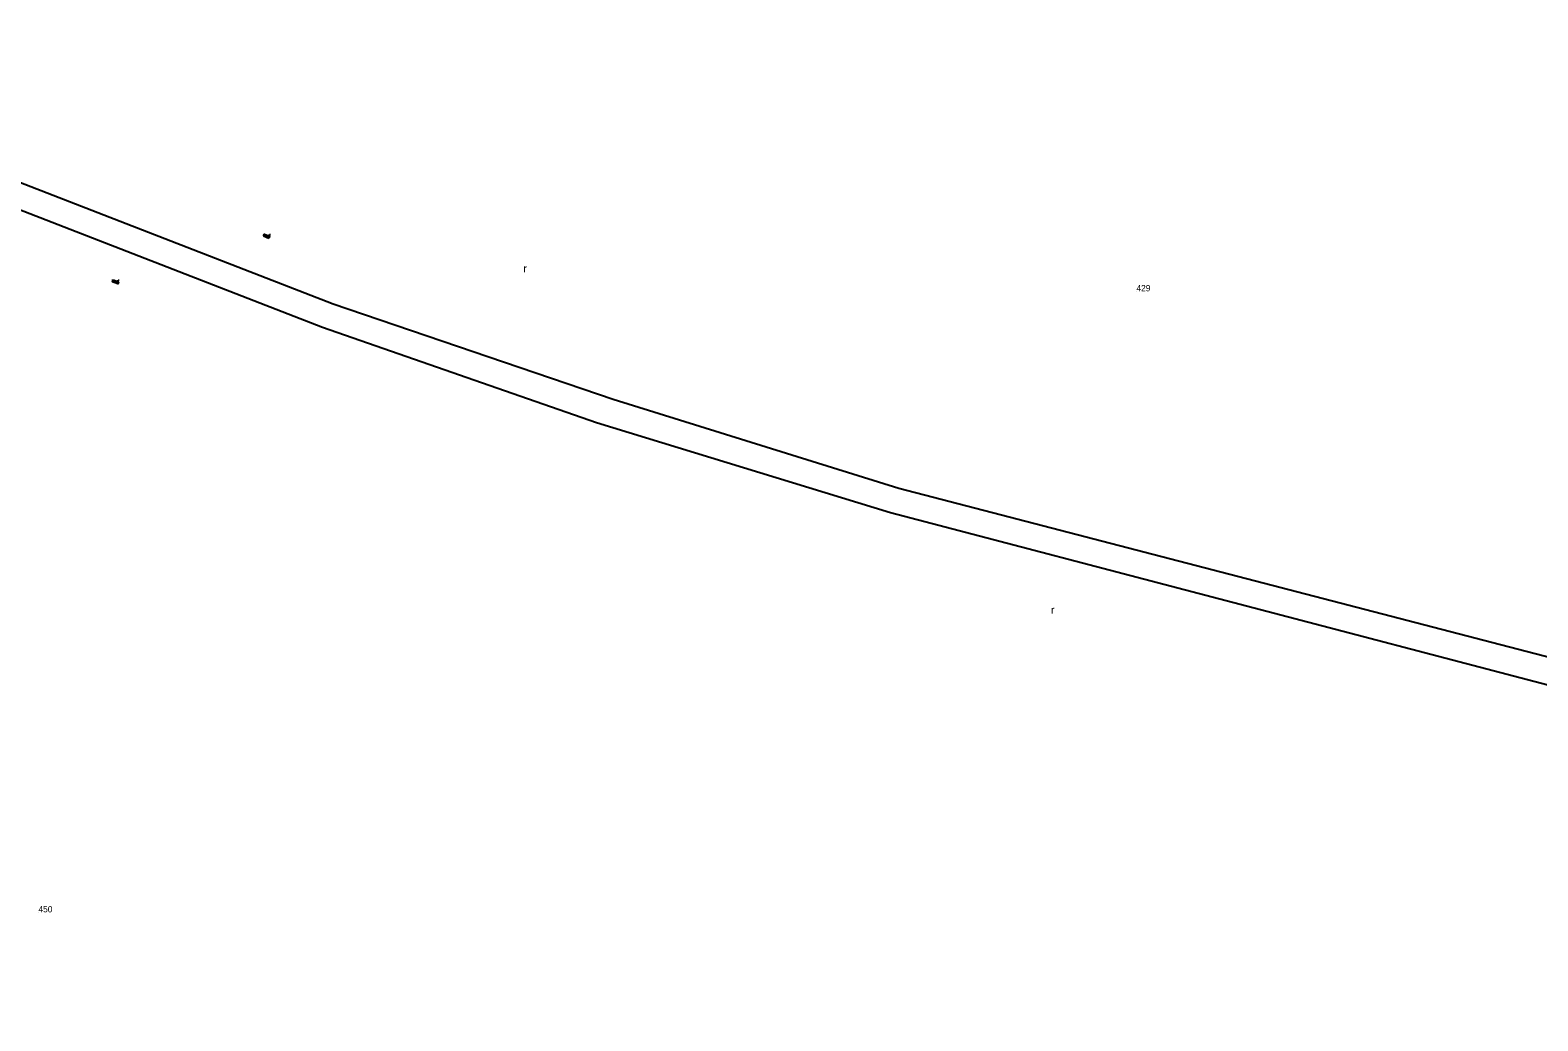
# Model space of a CAD drawing. Extents: x -836739 to -835945, y -1070775 to -1070126.
# Drawn here: x -836315.7 to -836135.3, y -1070524 to -1070405.6 of the extents above; entities that cross this region are included whole.
import ezdxf

# ---------------------------------------------------------------- set-up
doc = ezdxf.new("R2010")
doc.units = 0
for name, color, linetype in [('BodPole_mer', 7, 'Continuous'), ('Doprava_hranice', 7, 'Continuous'), ('OstPloch_kody', 7, 'Continuous'), ('PovrZnIS_hranice', 7, 'Continuous'), ('PovrZnIS_kody', 7, 'Continuous'), ('RuianPar_popis', 7, 'Continuous')]:
    doc.layers.add(name, color=color, linetype=linetype)

msp = doc.modelspace()

# ---------------------------------------------------------------- linework, layer by layer
at = {"layer": 'BodPole_mer'}
for p, q in [((-836287.77, -1070430.19), (-836287.77, -1070430.19)), ((-836287.77, -1070430.19), (-836287.77, -1070430.19)), ((-836287.67, -1070429.96), (-836287.67, -1070429.96)), ((-836287.67, -1070429.96), (-836287.67, -1070429.96)), ((-836287.15, -1070430.45), (-836287.15, -1070430.45)), ((-836287.15, -1070430.45), (-836287.15, -1070430.45)), ((-836287.05, -1070430.22), (-836287.05, -1070430.22)), ((-836287.05, -1070430.22), (-836287.05, -1070430.22)), ((-836305.86, -1070435.68), (-836305.86, -1070435.68)), ((-836305.86, -1070435.68), (-836305.86, -1070435.68)), ((-836305.78, -1070435.44), (-836305.78, -1070435.44)), ((-836305.78, -1070435.44), (-836305.78, -1070435.44)), ((-836305.22, -1070435.9), (-836305.22, -1070435.9)), ((-836305.22, -1070435.9), (-836305.22, -1070435.9)), ((-836305.14, -1070435.66), (-836305.14, -1070435.66)), ((-836305.14, -1070435.66), (-836305.14, -1070435.66)), ((-836279.43, -1070438.33), (-836279.43, -1070438.33)), ((-836280.73, -1070441.12), (-836280.73, -1070441.12)), ((-836245.95, -1070449.75), (-836245.95, -1070449.75)), ((-836247.95, -1070452.55), (-836247.95, -1070452.55)), ((-836211.76, -1070460.38), (-836211.76, -1070460.38)), ((-836212.77, -1070463.28), (-836212.77, -1070463.28))]:
    msp.add_line(p, q, dxfattribs=at)
at = {"layer": 'Doprava_hranice'}
for points in [[(-836015.21, -1070459.49), (-836021.84, -1070470.53), (-836029.29, -1070480.55), (-836039.31, -1070497.89), (-836043.1, -1070509.87), (-836044.22, -1070522.08), (-836111.13, -1070487.77), (-836123.74, -1070483.53), (-836128.61, -1070481.99), (-836211.76, -1070460.38), (-836245.95, -1070449.75), (-836279.43, -1070438.33), (-836363.94, -1070405.58)], [(-836046.6, -1070544.35), (-836045.64, -1070538.23), (-836044.38, -1070528.39), (-836045.14, -1070525.37), (-836047.92, -1070523.71), (-836112.97, -1070490.6), (-836124.66, -1070486.54), (-836132.47, -1070484.33), (-836212.77, -1070463.28), (-836247.95, -1070452.55), (-836280.73, -1070441.12), (-836361.89, -1070409.63)]]:
    msp.add_lwpolyline(points, dxfattribs=at)
at = {"layer": 'PovrZnIS_hranice'}
for p, q in [((-836287.77, -1070430.19), (-836287.15, -1070430.45)), ((-836287.77, -1070430.19), (-836287.15, -1070430.45)), ((-836305.78, -1070435.44), (-836305.14, -1070435.66)), ((-836305.78, -1070435.44), (-836305.14, -1070435.66))]:
    msp.add_line(p, q, dxfattribs=at)
for points in [[(-836287.77, -1070430.19), (-836287.67, -1070429.96), (-836287.05, -1070430.22), (-836287.15, -1070430.45)], [(-836287.77, -1070430.19), (-836287.67, -1070429.96), (-836287.05, -1070430.22), (-836287.15, -1070430.45)], [(-836305.14, -1070435.66), (-836305.22, -1070435.9), (-836305.86, -1070435.68), (-836305.78, -1070435.44)], [(-836305.14, -1070435.66), (-836305.22, -1070435.9), (-836305.86, -1070435.68), (-836305.78, -1070435.44)]]:
    msp.add_lwpolyline(points, dxfattribs=at)
at = {"layer": 'PovrZnIS_kody'}
for p, q in [((-836287.8, -1070430.02), (-836287.68, -1070430.02)), ((-836287.8, -1070430.02), (-836287.68, -1070430.02)), ((-836287.68, -1070430.02), (-836287.68, -1070430.22)), ((-836287.68, -1070430.02), (-836287.68, -1070430.22)), ((-836287.68, -1070430.22), (-836287.08, -1070430.22)), ((-836287.68, -1070430.22), (-836287.08, -1070430.22)), ((-836287.08, -1070430.22), (-836287.08, -1070430.02)), ((-836287.08, -1070430.02), (-836286.95, -1070430.02)), ((-836287.08, -1070430.22), (-836287.08, -1070430.02)), ((-836287.08, -1070430.02), (-836286.95, -1070430.02)), ((-836305.91, -1070435.47), (-836305.79, -1070435.47)), ((-836305.91, -1070435.47), (-836305.79, -1070435.47)), ((-836305.79, -1070435.47), (-836305.79, -1070435.67)), ((-836305.79, -1070435.47), (-836305.79, -1070435.67)), ((-836305.79, -1070435.67), (-836305.19, -1070435.67)), ((-836305.79, -1070435.67), (-836305.19, -1070435.67)), ((-836305.19, -1070435.67), (-836305.19, -1070435.47)), ((-836305.19, -1070435.47), (-836305.06, -1070435.47)), ((-836305.19, -1070435.67), (-836305.19, -1070435.47)), ((-836305.19, -1070435.47), (-836305.06, -1070435.47))]:
    msp.add_line(p, q, dxfattribs=at)
at = {"layer": 'RuianPar_popis'}
for p, q in [((-836183.35, -1070436.8), (-836183.35, -1070436.8)), ((-836314.71, -1070511.07), (-836314.71, -1070511.07))]:
    msp.add_line(p, q, dxfattribs=at)

# ---------------------------------------------------------------- texts
at = {"layer": 'OstPloch_kody'}
for p in [(-836256.69, -1070434.53), (-836193.57, -1070475.35)]:
    msp.add_text('r', height=0.9, dxfattribs=at).set_placement(p)
at = {"layer": 'RuianPar_popis'}
for s, p in [('429', (-836183.35, -1070436.8)), ('450', (-836314.71, -1070511.07))]:
    msp.add_text(s, height=0.75, dxfattribs=at).set_placement(p)

doc.saveas('drawing.dxf')
